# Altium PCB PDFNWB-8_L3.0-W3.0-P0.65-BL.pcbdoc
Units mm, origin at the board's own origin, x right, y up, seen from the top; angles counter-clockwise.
Board outline 16.18 x 16.92 mm, 2 copper layers (Top Layer, Bottom Layer), stack 0 mm thick; 1 components, 0 nets, 11 pads, 0 vias.
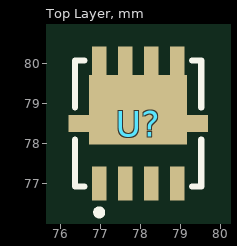
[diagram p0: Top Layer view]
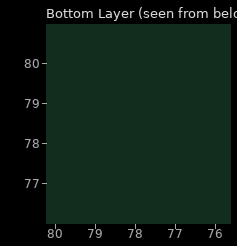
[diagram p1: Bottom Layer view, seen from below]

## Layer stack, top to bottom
Top Layer: signal copper (thickness not stored)
Bottom Layer: signal copper (thickness not stored)

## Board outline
86.03,69.85 69.85,69.85 69.85,86.769 86.03,86.769

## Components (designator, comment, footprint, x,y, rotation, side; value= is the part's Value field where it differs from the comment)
U? "" PDFNWB-8_L3.0-W3.0-P0.65-BL 77.94,78.497 r0 top

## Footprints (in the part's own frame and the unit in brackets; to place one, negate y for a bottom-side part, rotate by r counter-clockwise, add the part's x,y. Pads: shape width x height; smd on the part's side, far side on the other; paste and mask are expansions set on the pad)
PDFNWB-8_L3.0-W3.0-P0.65-BL [mil]
  rect 14.33x33.35 smd paste-3937.01 mask+2: 1(-38.39,-59) 2(-12.79,-59) 3(12.8,-59) 4(38.39,-59) 5(38.39,59) 6(12.8,59) 7(-12.79,59) 8(-38.39,59)
  rect 26.18x16.54 smd paste-3937.01 mask+2: 9(-55.41,0) 9(55.41,0)
  rect 96.46x68.31 smd paste-3937.01 mask+2: 9(0,13.48)
  silkscreen extent -62,-90 62,62

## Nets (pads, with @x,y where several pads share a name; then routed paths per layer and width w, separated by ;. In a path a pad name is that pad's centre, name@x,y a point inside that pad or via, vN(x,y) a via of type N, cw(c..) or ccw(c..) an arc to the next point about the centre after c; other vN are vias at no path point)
pads on no net: U?.1 U?.2 U?.3 U?.4 U?.5 U?.6 U?.7 U?.8 U?.9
